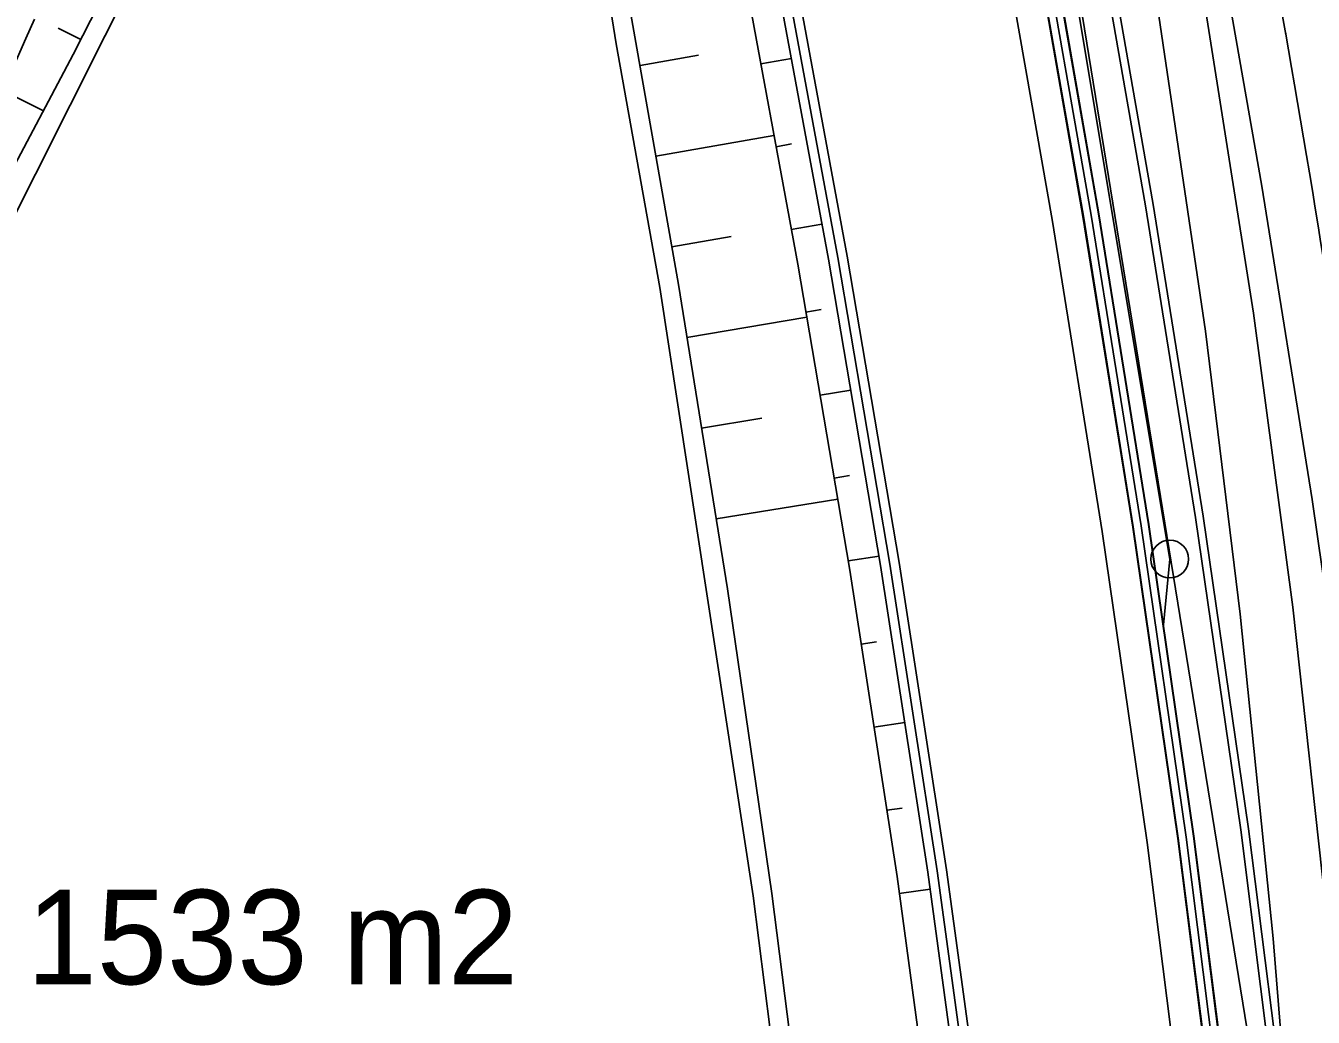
# Model space of a CAD drawing. Extents: x -440566 to -438466, y -1132677 to -1129707.
# Drawn here: x -439555.24 to -439514.34, y -1130295.81 to -1130264.3 of the extents above; entities that cross this region are included whole.
import ezdxf

# ---------------------------------------------------------------- set-up
doc = ezdxf.new("R2010")
doc.units = 0
for name, color, linetype in [('Vrstva 1', 7, 'Continuous'), ('Vrstva 15', 7, 'Continuous'), ('Vrstva 18', 7, 'Continuous'), ('Vrstva 3', 7, 'Continuous'), ('Vrstva 4', 7, 'Continuous'), ('Vrstva 5', 7, 'Continuous'), ('Vrstva 52', 7, 'Continuous'), ('Vrstva 8', 7, 'Continuous'), ('Vrstva 9', 7, 'Continuous')]:
    doc.layers.add(name, color=color, linetype=linetype)

msp = doc.modelspace()

# ---------------------------------------------------------------- linework, layer by layer
at = {"layer": 'Vrstva 1'}
msp.add_circle((-439546.225, -1130326.068), 100.196, dxfattribs=at)
at = {"layer": 'Vrstva 15'}
for p, q in [((-439553.488, -1130264.744), (-439554.21, -1130264.378)), ((-439535.725, -1130265.57), (-439533.863, -1130265.238)), ((-439531.888, -1130265.518), (-439530.915, -1130265.339)), ((-439554.677, -1130267.007), (-439555.965, -1130266.365)), ((-439535.22, -1130268.447), (-439531.469, -1130267.792)), ((-439531.404, -1130268.146), (-439530.916, -1130268.059)), ((-439530.919, -1130270.774), (-439529.944, -1130270.604)), ((-439534.715, -1130271.323), (-439532.826, -1130271)), ((-439534.234, -1130274.204), (-439530.428, -1130273.565)), ((-439530.455, -1130273.406), (-439529.967, -1130273.323)), ((-439530.007, -1130276.04), (-439529.03, -1130275.879)), ((-439533.769, -1130277.087), (-439531.852, -1130276.772)), ((-439529.558, -1130278.674), (-439529.07, -1130278.596)), ((-439533.304, -1130279.971), (-439529.444, -1130279.348)), ((-439529.11, -1130281.309), (-439528.132, -1130281.157)), ((-439528.698, -1130283.949), (-439528.209, -1130283.875)), ((-439528.292, -1130286.59), (-439527.312, -1130286.447)), ((-439527.885, -1130289.231), (-439527.395, -1130289.162)), ((-439527.488, -1130291.874), (-439526.507, -1130291.74))]:
    msp.add_line(p, q, dxfattribs=at)
at = {"layer": 'Vrstva 18'}
msp.add_line((-439518.897, -1130281.249), (-439519.1, -1130283.335), dxfattribs=at)
msp.add_lwpolyline([(-439562.927, -1130071.072), (-439561.912, -1130075.728), (-439557.438, -1130096.246), (-439552.963, -1130116.763), (-439548.489, -1130137.281), (-439544.014, -1130157.799), (-439539.54, -1130178.317), (-439535.066, -1130198.835), (-439530.612, -1130219.357), (-439526.311, -1130239.912), (-439522.342, -1130260.533), (-439518.897, -1130281.249)], dxfattribs=at)
msp.add_circle((-439518.897, -1130281.249), 0.6, dxfattribs=at)
at = {"layer": 'Vrstva 4'}
msp.add_lwpolyline([(-439566.273, -1130299.951), (-439560.765, -1130301.836), (-439554.249, -1130305.538), (-439558.213, -1130312.615), (-439559.98, -1130315.123), (-439525.556, -1130312.748), (-439529.11, -1130305.49), (-439530.87, -1130301.89), (-439532.13, -1130291.95), (-439535.1, -1130272.62), (-439536.48, -1130264.88), (-439536.79, -1130262.95), (-439538.61, -1130253.25), (-439540.53, -1130243.61), (-439541.61, -1130240.34), (-439543.65, -1130245.48), (-439548.81, -1130256.72), (-439549.41, -1130258.02), (-439556.03, -1130271.21), (-439566.273, -1130299.951)], dxfattribs=at)
at = {"layer": 'Vrstva 5'}
for points in [[(-439551.141, -1130102.825), (-439549.01, -1130112.596), (-439546.88, -1130122.366), (-439544.749, -1130132.136), (-439544.323, -1130134.091), (-439542.618, -1130141.907), (-439540.488, -1130151.677), (-439538.357, -1130161.448), (-439536.226, -1130171.218), (-439534.096, -1130180.988), (-439531.965, -1130190.759), (-439529.834, -1130200.529), (-439529.796, -1130200.706), (-439527.706, -1130210.305), (-439525.594, -1130220.096), (-439523.518, -1130229.906), (-439521.498, -1130239.738), (-439520.515, -1130244.664), (-439519.553, -1130249.597), (-439517.703, -1130259.485), (-439515.969, -1130269.405), (-439514.37, -1130279.359), (-439512.928, -1130289.348), (-439511.661, -1130299.371)], [(-439554.805, -1130103.624), (-439552.674, -1130113.395), (-439550.544, -1130123.165), (-439548.413, -1130132.935), (-439547.987, -1130134.89), (-439546.282, -1130142.706), (-439544.152, -1130152.476), (-439542.021, -1130162.247), (-439539.89, -1130172.017), (-439537.76, -1130181.787), (-439535.629, -1130191.558), (-439533.498, -1130201.328), (-439533.46, -1130201.505), (-439531.37, -1130211.101), (-439529.261, -1130220.881), (-439527.189, -1130230.673), (-439525.174, -1130240.48), (-439524.194, -1130245.39), (-439523.235, -1130250.306), (-439521.393, -1130260.154), (-439519.667, -1130270.027), (-439518.077, -1130279.926), (-439516.643, -1130289.852), (-439515.386, -1130299.805)], [(-439554.561, -1130103.571), (-439552.43, -1130113.341), (-439550.299, -1130123.112), (-439548.169, -1130132.882), (-439547.743, -1130134.836), (-439546.038, -1130142.653), (-439543.907, -1130152.423), (-439541.777, -1130162.193), (-439539.646, -1130171.964), (-439537.515, -1130181.734), (-439535.385, -1130191.504), (-439533.254, -1130201.275), (-439533.216, -1130201.452), (-439531.126, -1130211.048), (-439529.016, -1130220.829), (-439526.944, -1130230.622), (-439524.929, -1130240.43), (-439523.948, -1130245.342), (-439522.99, -1130250.259), (-439521.147, -1130260.11), (-439519.421, -1130269.985), (-439517.83, -1130279.888), (-439516.396, -1130289.818), (-439515.137, -1130299.776)], [(-439557.736, -1130104.264), (-439555.605, -1130114.034), (-439553.475, -1130123.804), (-439551.344, -1130133.575), (-439550.918, -1130135.529), (-439549.213, -1130143.345), (-439547.083, -1130153.115), (-439544.952, -1130162.886), (-439542.821, -1130172.656), (-439540.691, -1130182.427), (-439538.56, -1130192.197), (-439536.429, -1130201.967), (-439536.391, -1130202.144), (-439534.302, -1130211.737), (-439532.194, -1130221.509), (-439530.125, -1130231.286), (-439528.114, -1130241.073), (-439527.137, -1130245.971), (-439526.181, -1130250.873), (-439524.345, -1130260.689), (-439522.626, -1130270.524), (-439521.043, -1130280.379), (-439519.616, -1130290.255), (-439518.365, -1130300.153)], [(-439556.775, -1130104.054), (-439554.644, -1130113.824), (-439552.514, -1130123.595), (-439550.383, -1130133.365), (-439549.957, -1130135.319), (-439548.252, -1130143.135), (-439546.122, -1130152.906), (-439543.991, -1130162.676), (-439541.86, -1130172.447), (-439539.73, -1130182.217), (-439537.599, -1130191.987), (-439535.468, -1130201.758), (-439535.43, -1130201.935), (-439533.341, -1130211.529), (-439531.232, -1130221.303), (-439529.162, -1130231.085), (-439527.15, -1130240.878), (-439526.172, -1130245.781), (-439525.215, -1130250.689), (-439523.377, -1130260.515), (-439521.656, -1130270.362), (-439520.07, -1130280.232), (-439518.641, -1130290.125), (-439517.389, -1130300.036)], [(-439556.759, -1130104.051), (-439554.628, -1130113.821), (-439552.498, -1130123.591), (-439550.367, -1130133.362), (-439549.941, -1130135.316), (-439548.236, -1130143.132), (-439546.106, -1130152.902), (-439543.975, -1130162.673), (-439541.844, -1130172.443), (-439539.714, -1130182.214), (-439537.583, -1130191.984), (-439535.452, -1130201.754), (-439535.414, -1130201.931), (-439533.325, -1130211.525), (-439531.216, -1130221.3), (-439529.146, -1130231.082), (-439527.134, -1130240.875), (-439526.156, -1130245.778), (-439525.199, -1130250.685), (-439523.361, -1130260.511), (-439521.64, -1130270.359), (-439520.054, -1130280.228), (-439518.625, -1130290.121), (-439517.373, -1130300.033)], [(-439556.759, -1130104.051), (-439554.628, -1130113.821), (-439552.498, -1130123.591), (-439550.367, -1130133.362), (-439549.941, -1130135.316), (-439548.236, -1130143.132), (-439546.106, -1130152.902), (-439543.975, -1130162.673), (-439541.844, -1130172.443), (-439539.714, -1130182.214), (-439537.583, -1130191.984), (-439535.452, -1130201.754), (-439535.414, -1130201.931), (-439533.325, -1130211.525), (-439531.216, -1130221.3), (-439529.146, -1130231.082), (-439527.134, -1130240.875), (-439526.156, -1130245.778), (-439525.199, -1130250.684), (-439523.361, -1130260.511), (-439521.64, -1130270.358), (-439520.054, -1130280.228), (-439518.625, -1130290.121), (-439517.372, -1130300.037)], [(-439556.271, -1130103.944), (-439554.14, -1130113.714), (-439552.009, -1130123.485), (-439549.879, -1130133.255), (-439549.452, -1130135.209), (-439547.748, -1130143.025), (-439545.617, -1130152.796), (-439543.487, -1130162.566), (-439541.356, -1130172.337), (-439539.225, -1130182.107), (-439537.095, -1130191.877), (-439534.964, -1130201.648), (-439534.925, -1130201.825), (-439532.836, -1130211.419), (-439530.727, -1130221.195), (-439528.657, -1130230.98), (-439526.644, -1130240.775), (-439525.665, -1130245.681), (-439524.708, -1130250.592), (-439522.869, -1130260.422), (-439521.147, -1130270.276), (-439519.56, -1130280.153), (-439518.13, -1130290.054), (-439516.876, -1130299.972)], [(-439554.384, -1130113.768), (-439552.254, -1130123.538), (-439550.123, -1130133.308), (-439549.697, -1130135.262), (-439547.992, -1130143.079), (-439545.862, -1130152.849), (-439543.731, -1130162.619), (-439541.6, -1130172.39), (-439539.47, -1130182.16), (-439537.339, -1130191.931), (-439535.208, -1130201.701), (-439535.17, -1130201.878), (-439533.081, -1130211.472), (-439530.972, -1130221.247), (-439528.902, -1130231.031), (-439526.889, -1130240.826), (-439525.911, -1130245.729), (-439524.954, -1130250.637), (-439523.115, -1130260.466), (-439521.393, -1130270.317), (-439519.807, -1130280.19), (-439518.378, -1130290.087), (-439517.124, -1130300.008)], [(-439552.009, -1130123.485), (-439549.879, -1130133.255), (-439549.452, -1130135.209), (-439547.748, -1130143.025), (-439545.617, -1130152.796), (-439543.487, -1130162.566), (-439541.356, -1130172.337), (-439539.225, -1130182.107), (-439537.095, -1130191.877), (-439534.964, -1130201.648), (-439534.925, -1130201.825), (-439532.836, -1130211.419), (-439530.727, -1130221.195), (-439528.657, -1130230.979), (-439526.644, -1130240.776), (-439525.665, -1130245.681), (-439524.708, -1130250.59), (-439522.869, -1130260.422), (-439521.147, -1130270.275), (-439519.56, -1130280.152), (-439518.13, -1130290.054), (-439516.876, -1130299.979)], [(-439550.382, -1130133.365), (-439549.956, -1130135.319), (-439548.251, -1130143.135), (-439546.12, -1130152.906), (-439543.99, -1130162.676), (-439541.859, -1130172.446), (-439539.728, -1130182.217), (-439537.598, -1130191.987), (-439535.467, -1130201.757), (-439535.429, -1130201.934), (-439533.34, -1130211.528), (-439531.231, -1130221.302), (-439529.161, -1130231.085), (-439527.149, -1130240.879), (-439526.171, -1130245.78), (-439525.214, -1130250.686), (-439523.376, -1130260.513), (-439521.655, -1130270.361), (-439520.069, -1130280.23), (-439518.64, -1130290.123), (-439517.387, -1130300.041)], [(-439549.893, -1130133.258), (-439549.467, -1130135.212), (-439547.763, -1130143.029), (-439545.632, -1130152.799), (-439543.501, -1130162.569), (-439541.371, -1130172.34), (-439539.24, -1130182.11), (-439537.109, -1130191.881), (-439534.979, -1130201.651), (-439534.94, -1130201.828), (-439532.851, -1130211.422), (-439530.742, -1130221.198), (-439528.672, -1130230.982), (-439526.659, -1130240.779), (-439525.68, -1130245.684), (-439524.723, -1130250.592), (-439522.884, -1130260.424), (-439521.161, -1130270.278), (-439519.575, -1130280.155), (-439518.145, -1130290.056), (-439516.89, -1130299.981)], [(-439541.522, -1130213.864), (-439539.436, -1130223.059), (-439537.272, -1130232.779), (-439535.167, -1130242.496), (-439534.144, -1130247.354), (-439533.149, -1130252.214), (-439531.237, -1130261.938), (-439529.442, -1130271.669), (-439527.784, -1130281.41), (-439526.283, -1130291.16), (-439524.956, -1130300.922)], [(-439541.222, -1130213.833), (-439539.143, -1130222.996), (-439536.978, -1130232.717), (-439534.873, -1130242.436), (-439533.85, -1130247.296), (-439532.855, -1130252.158), (-439530.942, -1130261.885), (-439529.146, -1130271.62), (-439527.488, -1130281.364), (-439525.985, -1130291.12), (-439524.658, -1130300.887)], [(-439541.295, -1130216.222), (-439539.73, -1130223.121), (-439537.565, -1130232.84), (-439535.461, -1130242.555), (-439534.438, -1130247.412), (-439533.444, -1130252.271), (-439531.532, -1130261.992), (-439529.738, -1130271.719), (-439528.081, -1130281.455), (-439526.58, -1130291.201), (-439525.254, -1130300.957)], [(-439541.294, -1130216.2), (-439538.534, -1130233.043), (-439536.432, -1130242.751), (-439535.41, -1130247.604), (-439534.416, -1130252.458), (-439532.506, -1130262.169), (-439530.714, -1130271.883), (-439529.06, -1130281.605), (-439527.561, -1130291.334), (-439526.238, -1130301.072)], [(-439541.576, -1130238.52), (-439539.943, -1130243.459), (-439538.968, -1130248.306), (-439538.021, -1130253.152), (-439536.204, -1130262.839), (-439534.506, -1130272.52), (-439532.944, -1130282.198), (-439531.539, -1130291.874), (-439530.307, -1130301.547)]]:
    msp.add_lwpolyline(points, dxfattribs=at)
at = {"layer": 'Vrstva 52'}
for points in [[(-439519.288, -1130243.722), (-439518.376, -1130247.94), (-439516.728, -1130256.214), (-439515.21, -1130264.58)], [(-439519.282, -1130263.7), (-439517.758, -1130274.006), (-439516.66, -1130282.996)], [(-439517.816, -1130263.442), (-439516.234, -1130273.44), (-439514.984, -1130282.778)], [(-439516.66, -1130282.996), (-439515.61, -1130293.304), (-439514.878, -1130302.374)], [(-439514.984, -1130282.778), (-439513.854, -1130293.092), (-439513.016, -1130302.214)]]:
    msp.add_lwpolyline(points, dxfattribs=at)
msp.add_arc((-439955.983, -1130342.201), 447.555, 7.67284, 9.99697, dxfattribs=at)
at = {"layer": 'Vrstva 8'}
for points in [[(-439541.576, -1130238.52), (-439541.984, -1130239.658), (-439541.985, -1130239.659), (-439544.062, -1130244.92), (-439544.34, -1130245.585), (-439546.272, -1130250.033), (-439548.59, -1130255.009), (-439548.895, -1130255.639), (-439550.996, -1130259.86), (-439553.422, -1130264.615), (-439553.735, -1130265.22), (-439555.877, -1130269.281), (-439555.877, -1130269.281), (-439557.86, -1130274.051), (-439558.066, -1130274.678), (-439559.472, -1130278.908), (-439561.101, -1130283.712), (-439561.31, -1130284.326), (-439562.733, -1130288.466), (-439562.733, -1130288.467), (-439564.615, -1130293.789), (-439567.284, -1130301.334)], [(-439554.965, -1130264.092), (-439555.232, -1130264.708), (-439557.066, -1130268.857)]]:
    msp.add_lwpolyline(points, dxfattribs=at)
at = {"layer": 'Vrstva 9'}
msp.add_lwpolyline([(-439513.534, -1130343.19), (-439514.246, -1130323.552), (-439516.372, -1130296.598), (-439527.588, -1130227.558), (-439544.966, -1130158.304), (-439564.794, -1130097.324), (-439585.184, -1130025.212)], dxfattribs=at)

# ---------------------------------------------------------------- texts
at = {"layer": 'Vrstva 3'}
msp.add_text('1533 m2', height=3, dxfattribs=at).set_placement((-439555.21, -1130294.76))

doc.saveas('drawing.dxf')
